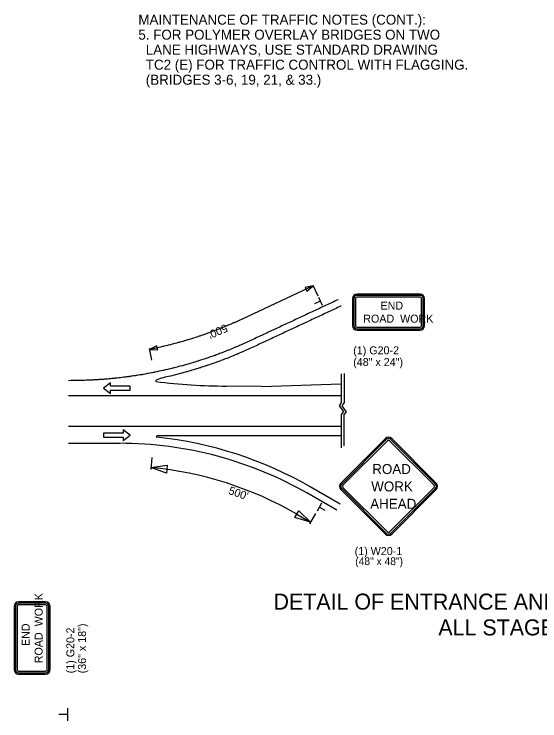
# Model space of a CAD drawing. Extents: x 1930579 to 1939784, y 596179 to 597522.
# Drawn here: x 1937895 to 1938290, y 596993 to 597522 of the extents above; entities that cross this region are included whole.
import ezdxf

# ---------------------------------------------------------------- set-up
doc = ezdxf.new("R2010")
doc.units = 0
for name, color, linetype in [('Default', 7, 'Continuous'), ('P_TC_Signs_Temporary', 7, 'Continuous'), ('R_Annotation', 7, 'Continuous'), ('R_Striping', 7, 'Continuous'), ('S_EDGE_PAVEMENT', 7, 'Continuous'), ('S_SHOULDER', 7, 'Continuous')]:
    doc.layers.add(name, color=color, linetype=linetype)

msp = doc.modelspace()

# ---------------------------------------------------------------- linework, layer by layer
at = {"layer": 'Default'}
for p, q in [((1938119.36, 597319.21), (1938123.16, 597311.05)), ((1938124.91, 597307.07), (1938120.73, 597305.12)), ((1938123.58, 597310.15), (1938126.43, 597304.03)), ((1937996.79, 597271.64), (1937998.56, 597262.81)), ((1937998.69, 597189.93), (1937997.9, 597180.97)), ((1938126.01, 597155.7), (1938122.64, 597149.85)), ((1938124.42, 597152.74), (1938128.41, 597150.44)), ((1938107.39, 597147.5), (1938117.78, 597141.5)), ((1938121.53, 597148), (1938117.03, 597140.2)), ((1937935.58, 597002.07), (1937935.58, 596992.58)), ((1937935.44, 596997.35), (1937928.96, 596997.35))]:
    msp.add_line(p, q, dxfattribs=at)
for points in [[(1938119.67, 597318.53), (1938066.36, 597293.67), (1938065.89, 597293.45), (1938064.79, 597292.94), (1938064.79, 597292.94), (1938063.69, 597292.44), (1938063.21, 597292.22), (1938062.6, 597291.95), (1938061.62, 597291.5), (1938061.51, 597291.46), (1938060.4, 597290.96), (1938060.04, 597290.81), (1938059.3, 597290.48), (1938058.44, 597290.11), (1938058.2, 597290.01), (1938057.08, 597289.53), (1938056.86, 597289.43), (1938055.98, 597289.06), (1938055.25, 597288.75), (1938054.92, 597288.61), (1938054.88, 597288.6), (1938053.76, 597288.13), (1938053.66, 597288.09), (1938052.65, 597287.68), (1938052.05, 597287.43), (1938051.54, 597287.23), (1938050.44, 597286.78), (1938050.42, 597286.78), (1938049.78, 597286.52), (1938049.3, 597286.33), (1938048.83, 597286.15), (1938048.18, 597285.89), (1938047.21, 597285.52), (1938047.06, 597285.46), (1938045.93, 597285.03), (1938045.6, 597284.9), (1938044.81, 597284.6), (1938043.97, 597284.29), (1938043.69, 597284.18), (1938042.54, 597283.76), (1938042.35, 597283.69), (1938041.42, 597283.35), (1938040.72, 597283.09), (1938040.29, 597282.94), (1938039.15, 597282.53), (1938039.09, 597282.51), (1938038.02, 597282.14), (1938037.45, 597281.94), (1938036.89, 597281.74), (1938035.8, 597281.37), (1938035.75, 597281.35), (1938034.6, 597280.96), (1938034.17, 597280.82), (1938033.47, 597280.58), (1938032.52, 597280.27), (1938032.33, 597280.21), (1938031.17, 597279.83), (1938030.88, 597279.74), (1938030.03, 597279.47), (1938029.22, 597279.21), (1938028.89, 597279.1), (1938027.73, 597278.74), (1938027.57, 597278.69), (1938026.58, 597278.39), (1938025.91, 597278.18), (1938025.44, 597278.04), (1938024.27, 597277.69), (1938024.26, 597277.68), (1938023.12, 597277.35), (1938022.59, 597277.19), (1938021.98, 597277.02), (1938020.91, 597276.71), (1938020.82, 597276.68), (1938019.65, 597276.35), (1938019.25, 597276.24), (1938018.5, 597276.03), (1938017.58, 597275.78), (1938017.35, 597275.72), (1938016.17, 597275.4), (1938015.91, 597275.33), (1938015.01, 597275.09), (1938014.23, 597274.88), (1938013.86, 597274.79), (1938012.68, 597274.48), (1938012.56, 597274.45), (1938011.52, 597274.19), (1938010.87, 597274.03), (1938010.35, 597273.9), (1938009.18, 597273.61), (1938008.01, 597273.33), (1938007.5, 597273.21), (1938006.84, 597273.06), (1938005.81, 597272.81), (1938005.67, 597272.78), (1938005.41, 597272.72), (1938004.49, 597272.51), (1938004.32, 597272.47), (1938004.13, 597272.43), (1938003.32, 597272.25), (1938002.43, 597272.05), (1938002.15, 597271.99), (1938000.96, 597271.74), (1938000.74, 597271.69), (1937999.79, 597271.49), (1937999.04, 597271.33), (1937998.62, 597271.24), (1937997.43, 597271), (1937997.34, 597270.98), (1937997.11, 597270.94), (1937997.11, 597270.94), (1937996.94, 597270.9)], [(1938140.78, 597252.77), (1938140.78, 597231.25), (1938139.12, 597228.78), (1938142.36, 597224.35), (1938140.66, 597222.3), (1938140.65, 597197.28)], [(1938142.83, 597252.97), (1938142.83, 597231.16), (1938141.17, 597228.69), (1938144.4, 597224.26), (1938142.7, 597222.22), (1938142.7, 597198.72)]]:
    msp.add_lwpolyline(points, dxfattribs=at)
for points in [[(1938114.87, 597314.63), (1938119.67, 597318.53), (1938113.6, 597317.35)], [(1938002.53, 597273.55), (1937996.94, 597270.9), (1938003.11, 597270.6)], [(1938009.69, 597178.33), (1937998.03, 597182.46), (1938010.26, 597184.31)], [(1938108.88, 597150.1), (1938117.78, 597141.5), (1938105.88, 597144.9)]]:
    msp.add_lwpolyline(points, close=True, dxfattribs=at)
msp.add_arc((1937972.34, 596913.58), 270.11, 60, 84.542, dxfattribs=at)
at = {"layer": 'P_TC_Signs_Temporary'}
for p, q in [((1938199.8, 597312.41), (1938152.55, 597312.41)), ((1938199.8, 597311.47), (1938152.55, 597311.47)), ((1938149.18, 597309.03), (1938149.18, 597288.78)), ((1938150.11, 597309.03), (1938150.11, 597288.78)), ((1938151.43, 597309.03), (1938151.43, 597288.78)), ((1938199.8, 597310.16), (1938152.55, 597310.16)), ((1938200.93, 597288.78), (1938200.93, 597309.03)), ((1938202.24, 597288.78), (1938202.24, 597309.03)), ((1938203.18, 597288.78), (1938203.18, 597309.03)), ((1938152.55, 597287.66), (1938199.8, 597287.66)), ((1938152.55, 597286.35), (1938199.8, 597286.35)), ((1938152.55, 597285.41), (1938199.8, 597285.41)), ((1938140.38, 597170.74), (1938173.79, 597204.15)), ((1938141.04, 597170.08), (1938174.45, 597203.49)), ((1938141.97, 597169.15), (1938175.38, 597202.56)), ((1938176.97, 597202.56), (1938210.38, 597169.15)), ((1938177.9, 597203.49), (1938211.31, 597170.08)), ((1938178.56, 597204.15), (1938211.97, 597170.74)), ((1938175.38, 597134.15), (1938141.97, 597167.56)), ((1938210.38, 597167.56), (1938176.97, 597134.15)), ((1938173.79, 597132.56), (1938140.38, 597165.97)), ((1938174.45, 597133.22), (1938141.04, 597166.63)), ((1938211.31, 597166.63), (1938177.9, 597133.22)), ((1938211.97, 597165.97), (1938178.56, 597132.56)), ((1937895.45, 597078.32), (1937895.45, 597031.07)), ((1937896.39, 597078.32), (1937896.39, 597031.07)), ((1937897.7, 597078.32), (1937897.7, 597031.07)), ((1937919.08, 597081.7), (1937898.83, 597081.7)), ((1937919.08, 597080.76), (1937898.83, 597080.76)), ((1937919.08, 597079.45), (1937898.83, 597079.45)), ((1937920.2, 597031.07), (1937920.2, 597078.32)), ((1937921.51, 597031.07), (1937921.51, 597078.32)), ((1937922.45, 597031.07), (1937922.45, 597078.32)), ((1937898.83, 597029.95), (1937919.08, 597029.95)), ((1937898.83, 597028.63), (1937919.08, 597028.63)), ((1937898.83, 597027.7), (1937919.08, 597027.7))]:
    msp.add_line(p, q, dxfattribs=at)
for centre, radius, start, end in [((1938152.55, 597309.03), 3.38, 90, 180), ((1938152.55, 597309.03), 2.44, 90, 180), ((1938199.8, 597309.03), 3.38, 360, 90), ((1938199.8, 597309.03), 2.44, 360, 90), ((1938152.55, 597309.03), 1.13, 90, 180), ((1938199.8, 597309.03), 1.13, 360, 90), ((1938152.55, 597288.78), 3.38, 180, 270), ((1938152.55, 597288.78), 2.44, 180, 270), ((1938152.55, 597288.78), 1.13, 180, 270), ((1938199.8, 597288.78), 2.44, 270, 360), ((1938199.8, 597288.78), 1.13, 270, 360), ((1938199.8, 597288.78), 3.38, 270, 360), ((1938176.18, 597201.77), 3.38, 45, 135), ((1938176.18, 597201.77), 2.44, 45, 135), ((1938176.18, 597201.77), 1.13, 45, 135), ((1938142.77, 597168.36), 3.37, 135, 225), ((1938142.77, 597168.36), 2.44, 135, 225), ((1938142.77, 597168.36), 1.12, 135, 225), ((1938209.59, 597168.36), 1.12, 315, 45), ((1938209.59, 597168.36), 2.44, 315, 45), ((1938209.59, 597168.36), 3.38, 315, 45), ((1938176.18, 597134.95), 3.38, 225, 315), ((1938176.18, 597134.95), 2.44, 225, 315), ((1938176.18, 597134.95), 1.13, 225, 315), ((1937898.83, 597078.32), 3.38, 90, 180), ((1937898.83, 597078.32), 2.44, 90, 180), ((1937898.83, 597078.32), 1.13, 90, 180), ((1937919.08, 597078.32), 3.38, 360, 90), ((1937919.08, 597078.32), 2.44, 360, 90), ((1937919.08, 597078.32), 1.13, 360, 90), ((1937898.83, 597031.07), 3.38, 180, 270), ((1937898.83, 597031.07), 2.44, 180, 270), ((1937898.83, 597031.07), 1.13, 180, 270), ((1937919.08, 597031.07), 2.44, 270, 360), ((1937919.08, 597031.07), 1.13, 270, 360), ((1937919.08, 597031.07), 3.38, 270, 360)]:
    msp.add_arc(centre, radius, start, end, dxfattribs=at)
at = {"layer": 'R_Striping'}
for points in [[(1937967.66, 597245.93), (1937962.46, 597241.93), (1937967.66, 597237.93), (1937967.66, 597240.43), (1937982.37, 597240.43), (1937982.37, 597243.43), (1937967.66, 597243.43)], [(1937977.18, 597202.68), (1937982.37, 597206.68), (1937977.18, 597210.68), (1937977.18, 597208.18), (1937962.46, 597208.18), (1937962.46, 597205.18), (1937977.18, 597205.18)]]:
    msp.add_lwpolyline(points, close=True, dxfattribs=at)
at = {"layer": 'S_EDGE_PAVEMENT'}
for p, q in [((1938080.95, 597243.08), (1938054.66, 597243.53)), ((1938080.95, 597243.08), (1938140.78, 597245.08)), ((1938140.65, 597206.08), (1938002.62, 597206.08))]:
    msp.add_line(p, q, dxfattribs=at)
for points in [[(1938140.56, 597303.45), (1938140.28, 597303.32), (1938139.15, 597302.79), (1938138.01, 597302.26), (1938136.88, 597301.73), (1938135.75, 597301.2), (1938134.61, 597300.68), (1938133.48, 597300.15), (1938132.35, 597299.62), (1938131.22, 597299.09), (1938130.08, 597298.56), (1938128.95, 597298.04), (1938127.82, 597297.51), (1938126.68, 597296.98), (1938125.55, 597296.45), (1938124.42, 597295.92), (1938123.29, 597295.39), (1938122.15, 597294.87), (1938121.02, 597294.34), (1938119.89, 597293.81), (1938118.75, 597293.28), (1938117.62, 597292.75), (1938116.49, 597292.22), (1938115.36, 597291.7), (1938114.22, 597291.17), (1938113.09, 597290.64), (1938111.96, 597290.11), (1938110.82, 597289.58), (1938109.69, 597289.05), (1938108.56, 597288.53), (1938107.43, 597288), (1938106.29, 597287.47), (1938105.16, 597286.94), (1938104.03, 597286.41), (1938102.89, 597285.88), (1938101.76, 597285.36), (1938100.63, 597284.83), (1938099.5, 597284.3), (1938098.36, 597283.77), (1938097.23, 597283.24), (1938097.16, 597283.21), (1938096.1, 597282.72), (1938094.96, 597282.19), (1938093.83, 597281.66), (1938093.02, 597281.28), (1938092.7, 597281.13), (1938091.57, 597280.6), (1938090.43, 597280.07), (1938089.3, 597279.55), (1938088.17, 597279.02), (1938087.03, 597278.49), (1938085.9, 597277.96), (1938084.77, 597277.43), (1938083.63, 597276.9), (1938083.29, 597276.74), (1938082.5, 597276.38), (1938081.37, 597275.85), (1938080.24, 597275.32), (1938079.1, 597274.79), (1938077.97, 597274.26), (1938076.84, 597273.73), (1938075.7, 597273.21), (1938074.57, 597272.68), (1938073.93, 597272.38), (1938073.44, 597272.15), (1938072.29, 597271.62), (1938072.28, 597271.62), (1938071.15, 597271.1), (1938070.64, 597270.86), (1938070.01, 597270.58), (1938068.98, 597270.12), (1938068.86, 597270.07), (1938067.71, 597269.56), (1938067.33, 597269.39), (1938066.56, 597269.05), (1938065.67, 597268.67), (1938065.4, 597268.55), (1938064.25, 597268.06), (1938064, 597267.95), (1938063.09, 597267.57), (1938062.33, 597267.25), (1938061.98, 597267.1), (1938061.93, 597267.08), (1938060.77, 597266.6), (1938060.66, 597266.55), (1938059.61, 597266.12), (1938058.98, 597265.87), (1938058.44, 597265.65), (1938057.3, 597265.19), (1938057.27, 597265.18), (1938056.61, 597264.91), (1938056.11, 597264.72), (1938055.62, 597264.52), (1938054.93, 597264.26), (1938053.93, 597263.87), (1938053.76, 597263.8), (1938052.59, 597263.35), (1938052.24, 597263.22), (1938051.41, 597262.91), (1938050.54, 597262.58), (1938050.23, 597262.47), (1938049.06, 597262.03), (1938048.84, 597261.95), (1938047.87, 597261.6), (1938047.14, 597261.33), (1938046.69, 597261.17), (1938045.51, 597260.75), (1938045.43, 597260.72), (1938044.32, 597260.33), (1938043.72, 597260.12), (1938043.13, 597259.92), (1938042.01, 597259.53), (1938041.94, 597259.51), (1938040.75, 597259.11), (1938040.3, 597258.95), (1938039.56, 597258.71), (1938038.58, 597258.38), (1938038.37, 597258.31), (1938037.17, 597257.93), (1938036.85, 597257.82), (1938035.97, 597257.54), (1938035.13, 597257.27), (1938034.78, 597257.16), (1938033.58, 597256.79), (1938033.4, 597256.73), (1938032.37, 597256.42), (1938031.67, 597256.2), (1938031.17, 597256.05), (1938029.97, 597255.69), (1938029.93, 597255.68), (1938028.76, 597255.33), (1938028.19, 597255.17), (1938027.55, 597254.98), (1938026.45, 597254.66), (1938026.35, 597254.63), (1938025.14, 597254.29), (1938024.71, 597254.17), (1938023.92, 597253.95), (1938022.96, 597253.69), (1938022.71, 597253.62), (1938021.5, 597253.29), (1938021.22, 597253.22), (1938020.28, 597252.97), (1938012.68, 597250.98)], [(1938139.98, 597154.95), (1938117.48, 597167.94)]]:
    msp.add_lwpolyline(points, dxfattribs=at)
for centre, radius, start, end in [((1938002.08, 597247.46), 0.5, 111.7269, 262.445), ((1938022.02, 597197.41), 54.38, 99.8871, 111.7269), ((1938054.01, 597639.03), 395.5, 262.445, 270.0944), ((1938002.62, 597205.58), 0.5, 90, 264.1755), ((1937973.3, 596918.22), 288.35, 60, 84.1755)]:
    msp.add_arc(centre, radius, start, end, dxfattribs=at)
at = {"layer": 'S_SHOULDER'}
for p, q in [((1938140.75, 597236.08), (1937936.24, 597236.08)), ((1938140.67, 597213.08), (1937936.24, 597213.08)), ((1937974.59, 597200.58), (1937936.24, 597200.58))]:
    msp.add_line(p, q, dxfattribs=at)
for points in [[(1938138.34, 597308.21), (1938138.06, 597308.08), (1938136.93, 597307.55), (1938135.79, 597307.02), (1938134.66, 597306.49), (1938133.53, 597305.96), (1938132.4, 597305.43), (1938131.26, 597304.91), (1938130.13, 597304.38), (1938129, 597303.85), (1938127.86, 597303.32), (1938126.73, 597302.79), (1938125.6, 597302.26), (1938124.47, 597301.74), (1938123.33, 597301.21), (1938122.2, 597300.68), (1938121.07, 597300.15), (1938119.93, 597299.62), (1938118.8, 597299.1), (1938117.67, 597298.57), (1938116.54, 597298.04), (1938115.4, 597297.51), (1938114.27, 597296.98), (1938113.14, 597296.45), (1938112, 597295.93), (1938110.87, 597295.4), (1938109.74, 597294.87), (1938108.61, 597294.34), (1938107.47, 597293.81), (1938106.34, 597293.28), (1938105.21, 597292.76), (1938104.07, 597292.23), (1938102.94, 597291.7), (1938101.81, 597291.17), (1938100.68, 597290.64), (1938099.54, 597290.11), (1938098.41, 597289.59), (1938097.28, 597289.06), (1938096.14, 597288.53), (1938095.01, 597288), (1938094.94, 597287.97), (1938093.88, 597287.47), (1938092.74, 597286.95), (1938091.61, 597286.42), (1938090.8, 597286.04), (1938090.48, 597285.89), (1938089.35, 597285.36), (1938088.21, 597284.83), (1938087.08, 597284.3), (1938085.95, 597283.78), (1938084.81, 597283.25), (1938083.68, 597282.72), (1938082.55, 597282.19), (1938081.42, 597281.66), (1938081.07, 597281.5), (1938080.28, 597281.13), (1938079.15, 597280.61), (1938078.02, 597280.08), (1938076.88, 597279.55), (1938075.75, 597279.02), (1938074.62, 597278.49), (1938073.49, 597277.96), (1938072.35, 597277.44), (1938071.71, 597277.14), (1938071.23, 597276.91), (1938070.1, 597276.39), (1938070.09, 597276.39), (1938068.98, 597275.88), (1938068.47, 597275.65), (1938067.85, 597275.37), (1938066.84, 597274.92), (1938066.72, 597274.86), (1938065.59, 597274.36), (1938065.22, 597274.2), (1938064.46, 597273.87), (1938063.58, 597273.49), (1938063.32, 597273.37), (1938062.19, 597272.89), (1938061.94, 597272.78), (1938061.05, 597272.4), (1938060.3, 597272.09), (1938059.96, 597271.95), (1938059.91, 597271.92), (1938058.77, 597271.45), (1938058.66, 597271.41), (1938057.62, 597270.98), (1938057.01, 597270.73), (1938056.48, 597270.52), (1938055.36, 597270.07), (1938055.33, 597270.06), (1938054.67, 597269.8), (1938054.18, 597269.6), (1938053.7, 597269.41), (1938053.03, 597269.15), (1938052.04, 597268.76), (1938051.87, 597268.7), (1938050.72, 597268.26), (1938050.37, 597268.13), (1938049.56, 597267.82), (1938048.71, 597267.5), (1938048.4, 597267.39), (1938047.24, 597266.96), (1938047.03, 597266.88), (1938046.08, 597266.53), (1938045.36, 597266.27), (1938044.92, 597266.11), (1938043.75, 597265.7), (1938043.68, 597265.67), (1938042.59, 597265.29), (1938042, 597265.08), (1938041.42, 597264.88), (1938040.32, 597264.5), (1938040.25, 597264.48), (1938039.08, 597264.08), (1938038.63, 597263.93), (1938037.91, 597263.69), (1938036.94, 597263.37), (1938036.73, 597263.3), (1938035.56, 597262.92), (1938035.24, 597262.82), (1938034.38, 597262.54), (1938033.55, 597262.28), (1938033.2, 597262.17), (1938032.02, 597261.8), (1938031.84, 597261.75), (1938030.84, 597261.43), (1938030.14, 597261.22), (1938029.65, 597261.08), (1938028.47, 597260.72), (1938028.43, 597260.71), (1938027.28, 597260.37), (1938026.73, 597260.21), (1938026.1, 597260.02), (1938025.01, 597259.71), (1938024.91, 597259.68), (1938023.72, 597259.35), (1938023.3, 597259.23), (1938022.53, 597259.01), (1938021.58, 597258.75), (1938021.33, 597258.69), (1938020.14, 597258.36), (1938019.86, 597258.29), (1938018.94, 597258.05), (1938018.14, 597257.83), (1938017.75, 597257.73), (1938016.55, 597257.42), (1938016.41, 597257.39), (1938015.35, 597257.12), (1938014.68, 597256.95), (1938014.15, 597256.82), (1938012.95, 597256.53), (1938012.95, 597256.53), (1938011.75, 597256.24), (1938011.22, 597256.11), (1938010.54, 597255.95), (1938009.49, 597255.71), (1938009.34, 597255.67), (1938009.07, 597255.61), (1938008.13, 597255.4), (1938007.95, 597255.36), (1938007.75, 597255.31), (1938006.93, 597255.13), (1938006.01, 597254.93), (1938005.72, 597254.86), (1938004.51, 597254.6), (1938004.27, 597254.55), (1938003.3, 597254.34), (1938002.52, 597254.18), (1938002.09, 597254.09), (1938000.88, 597253.85), (1938000.78, 597253.83), (1938000.55, 597253.78), (1938000.55, 597253.78), (1937999.66, 597253.6), (1937999.03, 597253.48), (1937998.45, 597253.37), (1937997.28, 597253.14), (1937997.24, 597253.13), (1937996.02, 597252.91), (1937995.68, 597252.84), (1937995.53, 597252.81), (1937994.8, 597252.68), (1937993.78, 597252.5), (1937993.59, 597252.46), (1937992.37, 597252.25), (1937992.02, 597252.19), (1937991.15, 597252.04), (1937990.26, 597251.89), (1937989.93, 597251.84), (1937988.71, 597251.64), (1937988.51, 597251.61), (1937987.49, 597251.44), (1937986.75, 597251.33), (1937986.26, 597251.25), (1937985.04, 597251.07), (1937984.98, 597251.06), (1937983.82, 597250.89), (1937983.22, 597250.8), (1937982.59, 597250.72), (1937981.46, 597250.56), (1937981.37, 597250.54), (1937980.14, 597250.38), (1937979.69, 597250.32), (1937979.63, 597250.31), (1937978.92, 597250.22), (1937977.92, 597250.09), (1937977.69, 597250.06), (1937976.46, 597249.91), (1937976.15, 597249.87), (1937975.23, 597249.77), (1937974.38, 597249.67), (1937974.01, 597249.62), (1937972.78, 597249.49), (1937972.61, 597249.47), (1937971.55, 597249.36), (1937970.84, 597249.28), (1937970.32, 597249.23), (1937969.09, 597249.11), (1937969.07, 597249.1), (1937967.86, 597248.99), (1937967.29, 597248.94), (1937966.62, 597248.88), (1937965.52, 597248.78), (1937965.39, 597248.77), (1937964.58, 597248.7), (1937964.16, 597248.67), (1937963.74, 597248.63), (1937962.93, 597248.57), (1937962.17, 597248.51), (1937961.97, 597248.5), (1937961.69, 597248.48), (1937960.46, 597248.39), (1937960.19, 597248.37), (1937959.23, 597248.3), (1937958.41, 597248.25), (1937957.99, 597248.23), (1937956.76, 597248.15), (1937956.63, 597248.14), (1937955.52, 597248.08), (1937954.85, 597248.05), (1937954.29, 597248.02), (1937953.07, 597247.96), (1937953.05, 597247.96), (1937951.82, 597247.91), (1937951.29, 597247.88), (1937950.58, 597247.86), (1937949.51, 597247.82), (1937949.34, 597247.81), (1937948.11, 597247.77), (1937947.73, 597247.76), (1937946.87, 597247.74), (1937945.95, 597247.71), (1937945.64, 597247.71), (1937944.4, 597247.68), (1937944.17, 597247.68), (1937943.15, 597247.66), (1937941.9, 597247.64), (1937940.65, 597247.62), (1937939.4, 597247.59), (1937938.15, 597247.57), (1937936.24, 597247.54)], [(1938137.35, 597150.41), (1938114.86, 597163.39)]]:
    msp.add_lwpolyline(points, dxfattribs=at)
msp.add_arc((1937974.59, 596917.48), 283.11, 60, 90, dxfattribs=at)

# ---------------------------------------------------------------- texts
at = {"layer": 'Default'}
for s, height, rotation, p in [("500'", 6, 203.3447, (1938053.9, 597290.14)), ("500'", 6, 340.7113, (1938055.66, 597162.81)), ('DETAIL OF ENTRANCE AND EXIT RAMPS', 12, 360, (1938089.94, 597075.96)), ('ALL STAGES', 12, 360, (1938213.53, 597056.62))]:
    msp.add_text(s, height=height, rotation=rotation, dxfattribs=at).set_placement(p)
at = {"layer": 'P_TC_Signs_Temporary'}
for s, rotation, p in [('END', 360, (1938170.15, 597300.78)), ('ROAD  WORK', 360, (1938157.22, 597291.03)), ('ROAD  WORK', 90, (1937916.83, 597035.74)), ('END', 90, (1937907.08, 597048.67))]:
    msp.add_text(s, height=6, rotation=rotation, dxfattribs=at).set_placement(p)
for s, p in [(' ROAD ', (1938161.16, 597177.57)), ('WORK', (1938163.19, 597164.55)), (' AHEAD ', (1938159.64, 597151.52))]:
    msp.add_text(s, height=7.5, dxfattribs=at).set_placement(p)
at = {"layer": 'R_Annotation'}
for s, height, rotation, p in [('MAINTENANCE OF TRAFFIC NOTES (CONT.): ', 7.5, 360, (1937988.6, 597514.34)), ('5. FOR POLYMER OVERLAY BRIDGES ON TWO', 7.5, 360, (1937988.6, 597503.09)), ('  LANE HIGHWAYS, USE STANDARD DRAWING', 7.5, 360, (1937988.6, 597491.84)), ('  TC2 (E) FOR TRAFFIC CONTROL WITH FLAGGING.  ', 7.5, 360, (1937988.6, 597480.59)), ('  (BRIDGES 3-6, 19, 21, & 33.)', 7.5, 360, (1937988.6, 597469.34)), ('(1) W20-1', 6, 360, (1938150.77, 597116.85)), ('(48" x 48")', 5.76, 360, (1938151.19, 597109.33)), ('(1) G20-2', 6, 90, (1937940.6, 597028.21)), ('(36" x 18")', 5.9996, 90, (1937949.35, 597028.21))]:
    msp.add_text(s, height=height, rotation=rotation, dxfattribs=at).set_placement(p)
for s, height, p in [('(1) G20-2', 6, (1938149.69, 597267.26)), ('(48" x 24")', 5.9996, (1938149.69, 597258.51))]:
    msp.add_text(s, height=height, dxfattribs=at).set_placement(p)

doc.saveas('drawing.dxf')
